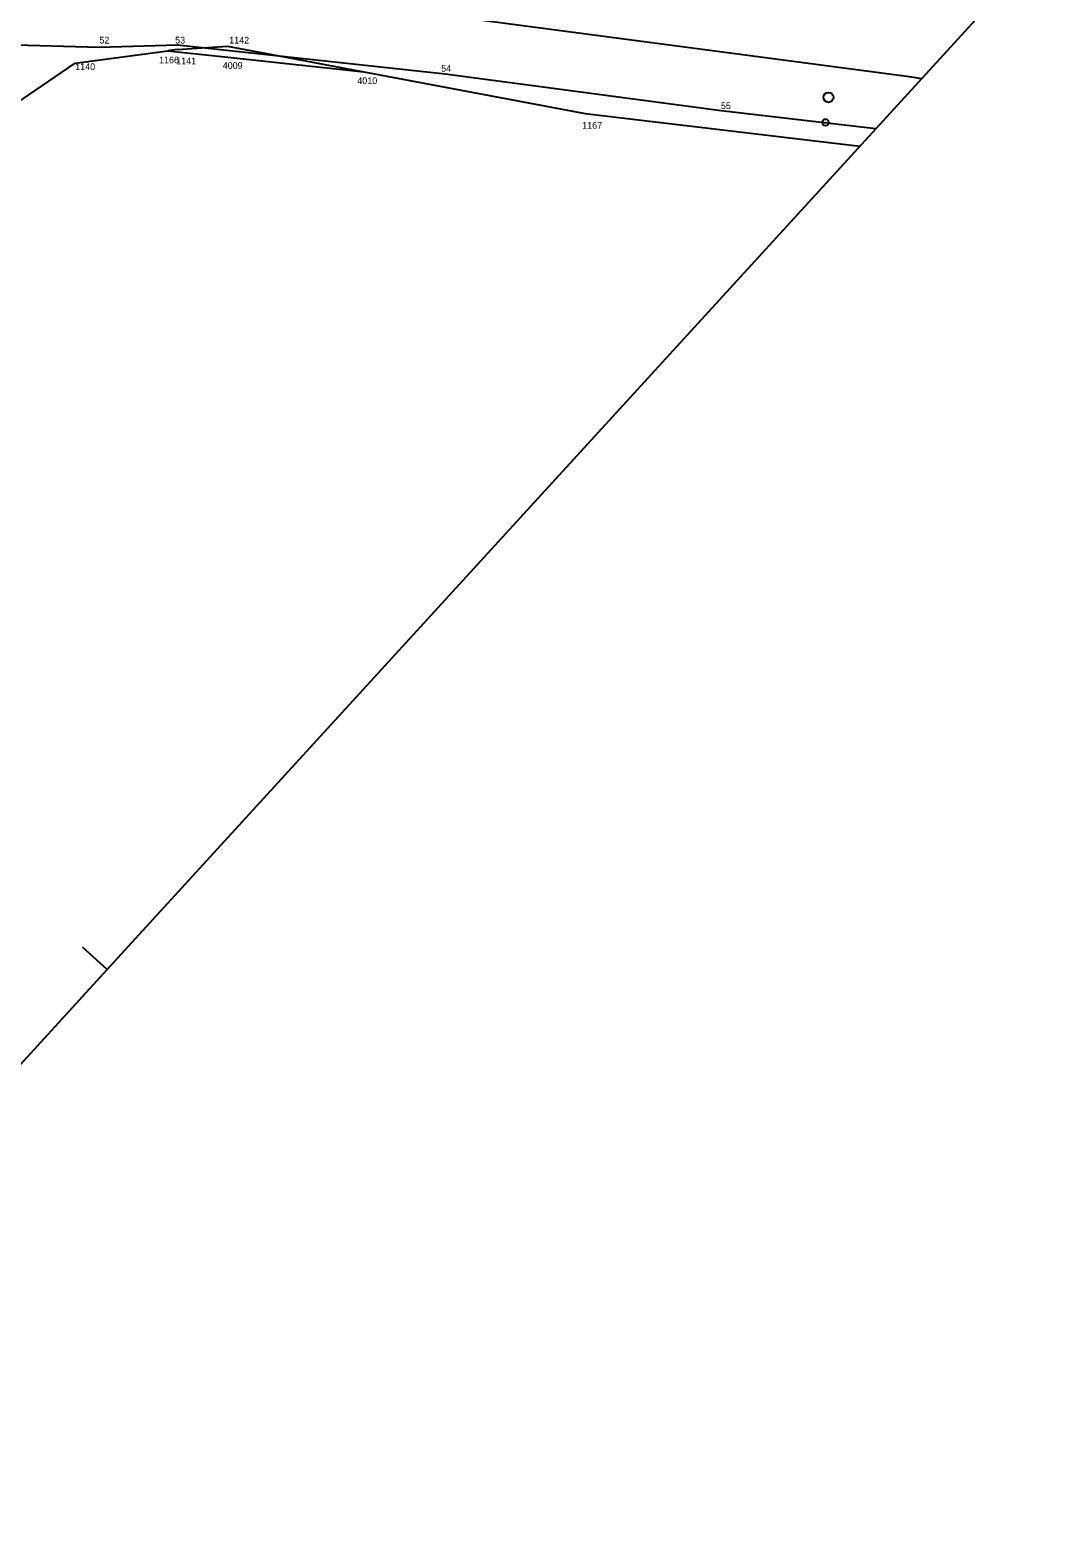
# Model space of a CAD drawing. Extents: x -678683 to -677755, y -1006946 to -1005971.
# Drawn here: x -678050.1 to -677896.9, y -1006566.2 to -1006341.2 of the extents above; entities that cross this region are included whole.
import ezdxf

# ---------------------------------------------------------------- set-up
doc = ezdxf.new("R2010")
doc.units = 0
for name, color, linetype in [('Dočasný zábor - do 1 roku', 7, 'Continuous'), ('Dočasný zábor_body', 7, 'Continuous'), ('rozpiska - Lichá Tisk', 7, 'Continuous'), ('SSZT nové - lomové body', 7, 'Continuous'), ('SSZT_nové', 7, 'Continuous'), ('SŽDC', 7, 'Continuous'), ('SŽDC - body', 7, 'Continuous'), ('Vrstva 7', 7, 'Continuous')]:
    doc.layers.add(name, color=color, linetype=linetype)

msp = doc.modelspace()

# ---------------------------------------------------------------- linework, layer by layer
at = {"layer": 'Dočasný zábor - do 1 roku'}
for p, q in [((-678029.55, -1006344.22), (-678021.01, -1006345.14)), ((-678021.01, -1006345.14), (-678000.24, -1006347.39))]:
    msp.add_line(p, q, dxfattribs=at)
at = {"layer": 'Dočasný zábor_body'}
for p, q in [((-678021.01, -1006345.14), (-678021.01, -1006345.14)), ((-678000.24, -1006347.39), (-678000.24, -1006347.39))]:
    msp.add_line(p, q, dxfattribs=at)
at = {"layer": 'rozpiska - Lichá Tisk'}
for p, q in [((-678038.61, -1006481.4), (-677896.87, -1006326.45)), ((-678038.61, -1006481.4), (-678042.3, -1006478.03)), ((-678180.35, -1006636.35), (-678038.61, -1006481.4))]:
    msp.add_line(p, q, dxfattribs=at)
at = {"layer": 'SSZT nové - lomové body'}
for p, q in [((-678039.76, -1006343.69), (-678039.76, -1006343.69)), ((-678028.1, -1006343.37), (-678028.1, -1006343.37)), ((-677988.11, -1006347.69), (-677988.11, -1006347.69)), ((-677946.88, -1006353.16), (-677946.88, -1006353.16))]:
    msp.add_line(p, q, dxfattribs=at)
at = {"layer": 'SSZT_nové'}
msp.add_lwpolyline([(-678199.43, -1006408.27), (-678188.69, -1006396.92), (-678166.33, -1006378.36), (-678141.21, -1006363.9), (-678122.02, -1006355.42), (-678102.99, -1006349.89), (-678082.69, -1006345.92), (-678069.35, -1006344.3), (-678054.02, -1006343.3), (-678039.76, -1006343.69), (-678028.1, -1006343.37), (-677988.11, -1006347.69), (-677946.88, -1006353.16), (-677923.77, -1006355.85)], dxfattribs=at)
at = {"layer": 'SŽDC'}
for p, q in [((-677918.4, -1006348.18), (-678022.51, -1006334.41)), ((-678028.13, -1006344.03), (-678029.55, -1006344.22)), ((-678028.13, -1006344.03), (-678020.64, -1006343.54)), ((-678020.64, -1006343.54), (-677967.17, -1006353.62)), ((-678060.24, -1006357.55), (-678043.36, -1006346.1)), ((-678043.36, -1006346.1), (-678029.55, -1006344.22)), ((-677916.96, -1006348.41), (-677918.4, -1006348.18)), ((-677967.17, -1006353.62), (-677926.18, -1006358.49))]:
    msp.add_line(p, q, dxfattribs=at)
at = {"layer": 'SŽDC - body'}
for p, q in [((-678028.13, -1006344.03), (-678028.13, -1006344.03)), ((-678020.64, -1006343.54), (-678020.64, -1006343.54)), ((-678043.36, -1006346.1), (-678043.36, -1006346.1)), ((-678029.55, -1006344.22), (-678029.55, -1006344.22)), ((-677918.4, -1006348.18), (-677918.4, -1006348.18)), ((-677967.17, -1006353.62), (-677967.17, -1006353.62))]:
    msp.add_line(p, q, dxfattribs=at)
at = {"layer": 'Vrstva 7'}
msp.add_line((-677931.33, -1006354.92), (-677931.23, -1006354.93), dxfattribs=at)
for centre, radius in [((-677930.85, -1006351.19), 0.75), ((-677931.28, -1006354.93), 0.5)]:
    msp.add_circle(centre, radius, dxfattribs=at)

# ---------------------------------------------------------------- texts
at = {"layer": 'Dočasný zábor_body'}
for s, p in [('4009', (-678021.33, -1006346.93)), ('4010', (-678001.22, -1006349.2))]:
    msp.add_text(s, height=1, dxfattribs=at).set_placement(p)
at = {"layer": 'SSZT nové - lomové body'}
for s, p in [('52', (-678039.75, -1006343.15)), ('53', (-678028.44, -1006343.15)), ('54', (-677988.69, -1006347.36)), ('55', (-677946.91, -1006352.93))]:
    msp.add_text(s, height=1, dxfattribs=at).set_placement(p)
at = {"layer": 'SŽDC - body'}
for s, p in [('1142', (-678020.36, -1006343.15)), ('1140', (-678043.36, -1006347.1)), ('1166', (-678030.84, -1006346.1)), ('1141', (-678028.27, -1006346.25)), ('1167', (-677967.63, -1006355.87))]:
    msp.add_text(s, height=1, dxfattribs=at).set_placement(p)

doc.saveas('drawing.dxf')
